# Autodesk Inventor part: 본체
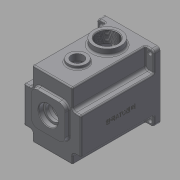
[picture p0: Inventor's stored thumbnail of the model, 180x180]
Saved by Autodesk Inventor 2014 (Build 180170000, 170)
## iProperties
Created: 2016-02
Part Number: 본체
Material: 일반
Document SubType Name: Modeling
Designer: mduedu
Density: 1 g/cm^3
Appearance: 기본값
Mass: 499.531 g
Surface Area: 1142.22 cm^2
Volume: 499.531 cm^3
Author: mduedu
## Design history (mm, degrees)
sketch "스케치1"
  geometry: L1 (-47, -47)-(47, -47); L2 (47, -47)-(47, 63); L3 (47, 63)-(-47, 63); L4 (-47, 63)-(-47, -47); 2 further points
  constraints: 8 end point, 2 parallel, 1 horizontal, 1 midpoint, 1 perpendicular, 1 vertical alignment
  dimensions: "d0" = 94 distance of L2.end L3.end; "d155" = 110 distance of L1.end L2.end; "d156" = 47 distance from line of L1 point (0, 0)
extrude "돌출1" new body sketch "스케치1" distance "d2" = 130; taper "d3" = 0 deg
sketch "스케치3"
  geometry: C1 r 40 at (0, 0); 1 further point
  constraints: 1 centre point, 1 coincident
  dimensions: "d9" = 80 diameter of C1
extrude "돌출3" cut sketch "스케치3" distance "d11" = 121; taper "d12" = 0 deg
sketch "스케치4"
  geometry: C1 r 21 at (0, 11); 1 further point
  constraints: 1 centre point, 1 vertical alignment
  dimensions: "d13" = 21 radius of C1; "d15" = 11 distance of point (0, 0) C1.centre
extrude "돌출4" join sketch "스케치4" distance "d16" = 7; taper "d17" = 0 deg
sketch "스케치5"
  geometry: C1 r 15 at (0, -20); 1 further point
  constraints: 1 centre point, 1 vertical alignment
  dimensions: "d18" = 15 radius of C1; "d20" = 20 distance of point (0, 0) C1.centre
extrude "돌출5" join sketch "스케치5" distance "d21" = 7; taper "d22" = 0 deg
sketch "스케치6"
  geometry: L1 (-28, -17)-(28, -17); L2 (28, -17)-(28, 39); L3 (28, 39)-(-28, 39); L4 (-28, 39)-(-28, -17); L5 (-28, -17)-(28, 39); L6 (28, -17)-(-28, 39); C1 r 28 at (0, 11); A1 r 21 centre (0, 11) between (8.978, -7.984) and (-8.978, -7.984) reference; 1 further point
  constraints: 12 end point, 2 midpoint, 2 parallel, 2 tangent, 1 centre point, 1 coincident, 1 horizontal, 1 perpendicular
  dimensions: "d23" = 56 diameter of C1
extrude "돌출6" join sketch "스케치6" distance "d25" = 7; taper "d26" = -3 deg
hole "구멍1" diameter "d29" = 35; stored, may be unused: countersink angle "d33" = 90 deg, drill point angle "d35" = 0 deg; dims "d27" = 10, "d28" = 10, "d30" = 6, "d31" = 4, "d32" = 2, "d34" = 10
hole "구멍2" diameter "d38" = 22; stored, may be unused: countersink angle "d42" = 90 deg, drill point angle "d44" = 0 deg; dims "d36" = 10, "d37" = 10, "d39" = 6, "d40" = 4, "d41" = 2, "d43" = 7
hole "구멍3" diameter "d47" = 19; stored, may be unused: countersink angle "d51" = 90 deg, drill point angle "d53" = 0 deg; dims "d45" = 10, "d46" = 10, "d48" = 6, "d49" = 4, "d50" = 2, "d52" = 1
hole "구멍4" diameter "d56" = 32; stored, may be unused: countersink angle "d60" = 90 deg, drill point angle "d62" = 0 deg; dims "d57" = 6, "d58" = 4, "d59" = 2, "d61" = 8, "d220" = 10, "d221" = 10
hole "구멍5" diameter "d65" = 25; stored, may be unused: countersink angle "d69" = 90 deg, drill point angle "d71" = 0 deg; dims "d63" = 10, "d64" = 10, "d66" = 6, "d67" = 4, "d68" = 2, "d70" = 8
fillet "모깎기2" dims "d73" = 0.3
fillet "모깎기3" dims "d74" = 2
chamfer "모따기1" distance "d75" = 1; stored, may be unused: second distance "d76" = 2, angle "d77" = 45 deg
fillet "모깎기4" dims "d78" = 3
sketch "스케치16"
  geometry: L1 (-23, 32.726)-(23, 32.726); L2 (23, 32.726)-(23, 53); L3 (23, 53)-(-23, 53); L4 (-23, 53)-(-23, 32.726); L5 (-47, 63)-(47, 63) reference; 3 further points
  constraints: 8 end point, 2 parallel, 1 horizontal, 1 midpoint, 1 perpendicular, 1 vertical alignment, 2 other
  dimensions: "d160" = 46 distance of L2.end L3.end; "d163" = 10 distance between parallel lines of L3 L5
extrude "돌출15" cut sketch "스케치16" stored distance "d164" = 10; taper "d165" = 0 deg
fillet "모깎기5" dims "d79" = 2
fillet "모깎기15" dims "d166" = 5
sketch "스케치7"
  geometry: L1 (-23, 48)-(-23, 35.228) reference; L2 (23, 35.228)-(23, 48) reference; L3 (18, 53)-(-18, 53) reference; L4 (47, 63)-(47, -47) reference; L5 (47, -47)-(-47, -47) reference; L6 (-47, -47)-(-47, 63) reference; L7 (-47, 63)-(47, 63) reference; L8 (-26, 48)-(-26, 35.228); L9 (26, 35.228)-(26, 48); L10 (18, 56)-(-18, 56); C1 r 43 at (0, 0); A1 r 5 centre (-18, 48) between (-18, 53) and (-23, 48) reference; A2 r 5 centre (-28, 35.228) between (-24.889, 31.314) and (-23, 35.228) reference; A3 r 40 centre (0, 0) between (-24.889, 31.314) and (24.889, 31.314) reference; A4 r 5 centre (28, 35.228) between (23, 35.228) and (24.889, 31.314) reference; A5 r 5 centre (18, 48) between (23, 48) and (18, 53) reference; A6 r 8 centre (-18, 48) between (-18, 56) and (-26, 48); A7 r 2 centre (-28, 35.228) between (-26.756, 33.662) and (-26, 35.228); A8 r 43 centre (0, 0) between (-26.756, 33.662) and (26.756, 33.662); A9 r 2 centre (28, 35.228) between (26, 35.228) and (26.756, 33.662); A10 r 8 centre (18, 48) between (26, 48) and (18, 56); 1 further point
  constraints: 10 point on circle, 6 centre point, 6 end point, 1 coincident, 7 other
  dimensions: "d80" = 86 diameter of C1; "d167" = 3 distance between parallel lines of L3 L10
extrude "돌출7" cut sketch "스케치7" distance "d83" = 9; taper "d84" = 0 deg
sketch "스케치8" dims "d168" = 36
  geometry: L1 (-36, 4)-(-39.799, 4); L2 (-36, -4)-(-39.799, -4); A1 r 4 centre (-36, 0) between (-36, 4) and (-36, -4); A2 r 40 centre (0, 0) between (-24.889, 31.314) and (24.889, 31.314) reference; A3 r 40 centre (0, 0) between (-39.799, 4) and (-39.799, -4); 2 further points
  constraints: 5 point on circle, 4 end point, 2 centre point, 2 coincident, 2 horizontal alignment, 2 tangent, 1 horizontal, 1 parallel, 2 other
  dimensions: "d169" = 4 radius of A1
extrude "돌출9" join sketch "스케치8" stored distance "d89" = 9; taper "d90" = 0 deg
fillet "모깎기6" dims "d91" = 3.5
node "작업 평면1"
sketch "스케치9"
  geometry: L1 (47, 63)-(33, 63); L2 (33, 63)-(33, 30); L3 (33, 30)-(47, 30); L4 (47, 30)-(47, 63); L5 (47, 63)-(-47, 63) reference; L6 (47, -47)-(47, 63) reference; A1 r 40 centre (0, 0) between (-39.148, -8.214) and (39.148, -8.214) reference; 1 further point
  constraints: 8 end point, 2 parallel, 1 coincident, 1 horizontal, 1 perpendicular
  dimensions: "d95" = 33 distance from line of L2 point (0, 0); "d96" = 30 distance from line of L3 point (0, 0)
extrude "돌출10" cut sketch "스케치9" distance "d97" = 110; taper "d98" = 0 deg
extrude "돌출21" cut sketch "스케치9" stored distance "d217" = 10; taper "d218" = 0 deg
sketch "스케치11" dims "d20" = 20
  geometry: L1 (-40, -40)-(40, -40); L2 (40, -40)-(40, 56); L3 (40, 56)-(-40, 56); L4 (-40, 56)-(-40, -40); L5 (-47, -47)-(47, -47) reference; L6 (47, 63)-(-47, 63) reference; L7 (-47, 63)-(-47, -47) reference; C1 r 3.5 at (-40, 56); C2 r 3.5 at (40, 56); C3 r 3.5 at (40, -40); C4 r 3.5 at (-40, -40); 1 further point
  constraints: 8 end point, 4 centre point, 4 coincident, 3 equal radius, 2 parallel, 1 horizontal, 1 perpendicular
  dimensions: "d109" = 80 distance of L2.end L3.end; "d112" = 7 diameter of C1; "d157" = 7 distance from line of L1.start L5; "d158" = 7 distance between parallel lines of L6 L3; "d159" = 7 distance from line of L7 L3.end
extrude "돌출12" cut sketch "스케치11" stored distance "d113" = 63; taper "d114" = 0 deg
fillet "모깎기7" dims "d115" = 5, "d187" = 5
fillet "모깎기8" dims "d116" = 5
fillet "모깎기18" dims "d219" = 2
fillet "모깎기12" dims "d120" = 2
fillet "모깎기13" dims "d121" = 2
sketch "스케치12"
  geometry: 3 further points
  constraints: 2 horizontal alignment
hole "구멍6" sketch "스케치12" at (36, 0), (-36, 0) diameter "d122" = 3.242; stored, may be unused: countersink angle "d126" = 90 deg, drill point angle "d128" = 120 deg; dims "d123" = 7, "d124" = 4, "d125" = 2, "d127" = 9
fillet "모깎기14" dims "d147" = 10
chamfer "모따기4" distance "d151" = 1; stored, may be unused: second distance "d152" = 2, angle "d153" = 45 deg
sketch "스케치20"
  geometry: L1 (73, -12)-(73, -130) reference; L2 (84, -8)-(77, -8) reference; L3 (84, 0)-(84, -8) reference; L4 (84, 0)-(0, 0) reference; L5 (7, -8)-(0, -8) reference; L6 (11, -130)-(11, -12) reference; L7 (0, -8)-(0, 0) reference; L8 (73, -130)-(11, -130) reference; L9 (42, 0)-(42, -130); C1 r 10 at (42, -89); A1 r 4 centre (77, -12) between (77, -8) and (73, -12) reference; A2 r 4 centre (7, -12) between (11, -12) and (7, -8) reference
  constraints: 2 end point, 1 centre point, 1 midpoint, 1 point on line
  dimensions: "d189" = 20 diameter of C1; "d190" = 41 distance from line of C1.centre L8
extrude "돌출19" cut sketch "스케치20" stored distance "d191" = 10; taper "d192" = 0 deg
sketch "스케치18"
  geometry: C1 r 15 at (42, -89); C2 r 10 at (42, -89) reference; 1 further point
  constraints: 1 centre point, 1 concentric
  dimensions: "d174" = 30 diameter of C1
extrude "돌출17" join sketch "스케치18" distance "d175" = 5; taper "d176" = 0 deg
fillet "모깎기16" dims "d177" = 2
sketch "스케치19"
  geometry: C1 r 10 at (18, 80) reference; C2 r 15 at (18, 80); 1 further point
  constraints: 1 centre point, 1 coincident
  dimensions: "d178" = 30 diameter of C2
extrude "돌출18" cut sketch "스케치19" distance "d181" = 5; taper "d182" = 0 deg
chamfer "모따기5" distance "d183" = 0.5; stored, may be unused: second distance "d184" = 2, angle "d185" = 45 deg
sketch "스케치21"
  geometry: L1 (-12, 14)-(-130, 14) reference; L2 (-8, 0)-(-8, 10) reference; L3 (0, 0)-(0, 100) reference; L4 (-8, 100)-(0, 100) reference; L5 (-8, 74)-(-8, 100) reference; L6 (-130, 70)-(-12, 70) reference; L7 (-130, 14)-(-130, 70) reference; L8 (0, 0)-(-8, 0) reference; L9 (-130, 14)-(-130, 70) reference; L10 (27.4, 42)-(-164.4, 42) reference; A1 r 4 centre (-12, 74) between (-12, 70) and (-8, 74) reference; A2 r 4 centre (-12, 10) between (-8, 10) and (-12, 14) reference; 3 further points
  constraints: 1 coincident, 1 point on line, 1 other
  dimensions: "d222" = 65 distance from line of point (-65, 42) L9
feature "엠보싱2" sketch "스케치21" dims "d20" = 20, "d193" = 0.5, "d194" = 0
sketch "스케치22"
  geometry: L1 (73, -12)-(73, -130) reference; L2 (84, -8)-(77, -8) reference; L3 (84, 0)-(84, -8) reference; L4 (84, 0)-(0, 0) reference; L5 (7, -8)-(0, -8) reference; L6 (11, -130)-(11, -12) reference; L7 (0, -8)-(0, 0) reference; L8 (73, -130)-(11, -130) reference; L9 (42, -130)-(42, 0); C1 r 17 at (42, -89) reference; C2 r 22.5 at (42, -40); A1 r 4 centre (77, -12) between (77, -8) and (73, -12) reference; A2 r 4 centre (7, -12) between (11, -12) and (7, -8) reference
  constraints: 2 end point, 1 centre point, 1 midpoint, 1 point on line
  dimensions: "d195" = 45 diameter of C2; "d197" = 40 distance from line of C2.centre L4
extrude "돌출20" join sketch "스케치22" distance "d198" = 10; taper "d199" = 0 deg
fillet "모깎기17" dims "d200" = 3
hole "구멍7" diameter "d203" = 33.376; stored, may be unused: countersink angle "d207" = 90 deg, drill point angle "d209" = 118 deg; dims "d204" = 6, "d205" = 4, "d206" = 2, "d208" = 8, "d223" = 10, "d224" = 10
chamfer "모따기6" distance "d210" = 1; stored, may be unused: second distance "d211" = 2, angle "d212" = 45 deg
fillet "모깎기19" dims "d225" = 2
node "솔리드1"
pattern_circular "원형 패턴1" dims angle "d93" = 360 deg
mirror "대칭1"
mirror "대칭2"
node "투영된 루프1"
node "투영된 루프2"
node "투영된 루프3"
node "절단 모서리 투영3"
